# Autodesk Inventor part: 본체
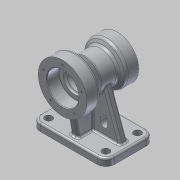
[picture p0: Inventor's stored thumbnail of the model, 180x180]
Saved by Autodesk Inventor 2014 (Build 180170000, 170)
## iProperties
Created: 2015-08
Part Number: 본체
Material: 알루미늄 6061
Document SubType Name: Modeling
Designer: net
Density: 2.71 g/cm^3
Appearance: 알루미늄 - 평지
Mass: 1062.72 g
Surface Area: 748.443 cm^2
Volume: 392.148 cm^3
Author: net
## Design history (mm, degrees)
sketch "스케치1"
  geometry: L1 (-61, 40)-(61, 40); L2 (61, 40)-(61, -40); L3 (61, -40)-(-61, -40); L4 (-61, -40)-(-61, 40); 1 further point
  constraints: 8 end point, 2 parallel, 1 horizontal, 1 perpendicular
  dimensions: "d0" = 122 distance between parallel lines of L2 L4; "d1" = 80 distance between parallel lines of L3 L1; "d2" = 40 distance from line of point (0, 0) L1; "d3" = 61 distance from line of point (0, 0) L4
extrude "돌출1" new body sketch "스케치1" distance "d4" = 12; taper "d5" = 0 deg
fillet "모깎기1" dims "d6" = 14
fillet "모깎기2" dims "d7" = 3
sketch "스케치2"
  geometry: L1 (-47, 37)-(47, 37) reference; L2 (-58, -26)-(-58, 26) reference; C1 r 6 at (-47, 26); C2 r 6 at (-47, -26); C3 r 6 at (47, 26); C4 r 6 at (47, -26); A1 r 11 centre (-47, 26) between (-47, 37) and (-58, 26) reference; 1 further point
  constraints: 4 centre point, 1 coincident, 1 horizontal, 1 vertical, 6 other
  dimensions: "d8" = 12 diameter of C1; "d11" = 52 distance of C1.centre C2.centre; "d14" = 94 distance of C1.centre C3.centre
extrude "돌출2" cut sketch "스케치2" stored distance "d17" = 12; taper "d18" = 0 deg
node "작업 평면1"
sketch "스케치3"
  geometry: L1 (0, 69.591)-(0, -74.026); L2 (35, 40)-(35, 20); L3 (35, 20)-(26, 14.804); L4 (26, 14.804)-(26, -13.315); L5 (26, -13.315)-(40, -30); L6 (40, -30)-(40, -50); L7 (0, 40)-(0, -50); L8 (35, 40)-(20, 40); L9 (20, 40)-(20, 23); L10 (20, 23)-(16, 23); L11 (16, 23)-(16, -27); L12 (26, -30)-(26, -50); L13 (26, -50)-(40, -50); L14 (47, 40)-(-47, 40) reference; L15 (26, -30)-(19, -30); L16 (19, -30)-(19, -27); L17 (19, -27)-(16, -27); 1 further point
  constraints: 32 end point, 8 parallel, 3 perpendicular, 2 point on line, 1 collinear, 1 vertical
  dimensions: "d20" = 70 diameter of L2 L1; "d22" = 60 deg angle of L4 L3; "d24" = 40 deg angle of L4 L5; "d25" = 20 distance of L5.end L6.end; "d26" = 80 diameter of L6 L1; "d27" = 52 diameter of L4 L1; "d29" = 0 distance from line of point (0, 0) L1; "d30" = 40 diameter of L9 L1; "d31" = 0 distance between parallel lines of L8 L14; "d36" = 90 distance between parallel lines of L13 L8; "d37" = 52 diameter of L12 L1; "d38" = 32 diameter of L11 L1; "d39" = 20 distance from line of L2.end L14; "d90" = 17 distance between parallel lines of L10 L14; "d91" = 20 distance between parallel lines of L13 L15; "d92" = 3 distance between parallel lines of L15 L17; "d93" = 38 diameter of L16 L1
revolve "회전1" sketch "스케치3" stored, may be unused: angle "d40" = 90 deg
fillet "모깎기3" dims "d41" = 5
fillet "모깎기4" dims "d42" = 0.3
chamfer "모따기1" distance "d44" = 1; stored, may be unused: second distance "d45" = 2, angle "d46" = 45 deg
sketch "스케치4"
  geometry: L1 (47, 12)-(58, 12) reference; L2 (-58, 12)-(-47, 12) reference; L3 (25.091, 83.185)-(51, 12); L4 (61, 0)-(61, 9) reference; L5 (0, 90)-(0, 0); L6 (-25.091, 83.185)-(-51, 12); L7 (49.162, 12)-(-51, 12); A1 r 26 centre (0, 90) between (-25.091, 83.185) and (25.091, 83.185)
  constraints: 8 end point, 2 point on circle, 2 point on line, 2 symmetric about line, 1 centre point, 1 coincident, 1 collinear, 1 parallel, 2 other
  dimensions: "d47" = 70 deg angle of L3 L1; "d48" = 10 distance from line of L4 L3.end
extrude "돌출3" join sketch "스케치4" stored distance "d49" = 12; taper "d50" = 0 deg
fillet "모깎기6" dims "d51" = 3
sketch "스케치5"
  geometry: L1 (47.807, 12)-(-47.807, 12) reference; L2 (-30, 36)-(-30, 30); L3 (-18, 30)-(-18, 36); L4 (0, 90)-(0, 12); L5 (47, 0)-(-47, 0) reference; A1 r 26 centre (0, 90) between (-23.481, 78.836) and (23.481, 78.836) reference; A2 r 6 centre (-24, 30) between (-30, 30) and (-18, 30); A3 r 6 centre (-24, 36) between (-18, 36) and (-30, 36); 1 further point
  constraints: 6 end point, 4 point on circle, 4 tangent, 2 centre point, 1 midpoint, 1 parallel, 1 perpendicular
  dimensions: "d52" = 18 dimension on A2 A3; "d53" = 12 distance between parallel lines of L3 L2; "d54" = 24 distance from line of L4 A2.centre; "d55" = 30 distance from line of L5 A2.centre
extrude "돌출4" cut sketch "스케치5" stored distance "d56" = 10; taper "d57" = 0 deg
sketch "스케치6"
  geometry: L1 (40, 55)-(22.887, 55) reference; L2 (26, 12)-(37, 12) reference; L3 (30, 55)-(30, 12); L4 (40, 9)-(40, 0) reference; 1 further point
  constraints: 2 end point, 2 point on line, 1 perpendicular
  dimensions: "d58" = 10 distance between parallel lines of L4 L3
feature "리브1" sketch "스케치6" dims "d59" = 1, "d60" = 12, "d61" = 0, "d62" = 0, "d63" = 1, "d64" = 1
sketch "스케치7"
  geometry: L1 (-31.82, 50)-(-50, 50) reference; L2 (-37, 12)-(-26, 12) reference; L3 (-36.7, 50)-(-30, 12); L4 (-40, 0)-(-40, 9) reference; 1 further point
  constraints: 2 end point, 2 point on line
  dimensions: "d66" = 80 deg angle of L3 L2; "d67" = 10 distance from line of L3.end L4
feature "리브2" sketch "스케치7" dims "d68" = 1, "d69" = 12, "d70" = 0, "d71" = 0, "d72" = 1, "d73" = 1
fillet "모깎기7" dims "d74" = 3
fillet "모깎기8" dims "d75" = 3
fillet "모깎기9" dims "d76" = 3
fillet "모깎기10" dims "d94" = 3
sketch "스케치8" dims "d77" = 66
  geometry: L1 (0, 33)-(0, 0); C1 r 27 at (0, 0) reference; C2 r 40 at (0, 0) reference; 6 further points
  constraints: 2 coincident, 2 end point, 1 vertical, 1 vertical alignment, 8 other
  dimensions: "d80" = 360 deg dimension on C1.centre point (0, 33) (derived)
hole "구멍1" sketch "스케치8" at (0, 33), (-31.385, 10.198), (-19.397, -26.698), (19.397, -26.698), (31.385, 10.198) diameter "d82" = 3.242; stored, may be unused: countersink angle "d86" = 90 deg, drill point angle "d88" = 118 deg; dims "d83" = 10, "d84" = 4, "d85" = 2, "d87" = 13
sketch "스케치10" dims "d110" = 54
  geometry: C1 r 21 at (0, 0) reference; C2 r 35 at (0, 0) reference; 7 further points
  constraints: 2 vertical alignment, 1 coincident, 8 other
  dimensions: "d113" = 360 deg dimension on C1.centre point (0, -27) (derived)
hole "구멍3" sketch "스케치10" at (0, -27), (25.679, -8.343), (15.87, 21.843), (-15.87, 21.843), (-25.679, -8.343) diameter "d115" = 3.242; stored, may be unused: countersink angle "d119" = 90 deg, drill point angle "d121" = 118 deg; dims "d116" = 10, "d117" = 4, "d118" = 2, "d120" = 13
node "솔리드1"
mirror "대칭1"
